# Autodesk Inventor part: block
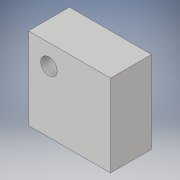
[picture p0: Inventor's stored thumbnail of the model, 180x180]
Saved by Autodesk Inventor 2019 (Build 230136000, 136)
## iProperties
Created: 2020-09
Part Number: block
Material: 一般
Document SubType Name: Modeling
Designer: kikut
Density: 1 g/cm^3
Appearance: 既定
Author: kikut
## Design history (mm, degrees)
sketch "スケッチ1"
  geometry: L1 (10, -10)-(-10, -10); L2 (-10, -10)-(-10, 10); L3 (-10, 10)-(10, 10); L4 (10, 10)-(10, -10); L5 (10, -10)-(-10, 10); L6 (-10, -10)-(10, 10); 1 further point
  constraints: 12 end point, 2 midpoint, 2 parallel, 1 horizontal, 1 perpendicular
  dimensions: "d0" = 20 distance of L1.end L2.end; "d1" = 20 distance of L2.end L3.end
extrude "押し出し1" new body sketch "スケッチ1" distance "d2" = 10; taper "d3" = 0 deg
sketch "スケッチ2"
  geometry: C1 r 2 at (-5, 5); 1 further point
  constraints: 1 centre point
  dimensions: "d4" = 4 diameter of C1; "d5" = 5 horizontal distance of point (0, 0) C1.centre; "d6" = 5 horizontal distance of point (0, 0) C1.centre
extrude "押し出し2" cut sketch "スケッチ2" extent not by distance; stored distance "d7" = 5 (= d6); taper "d8" = 0 deg
node "ソリッド1"
